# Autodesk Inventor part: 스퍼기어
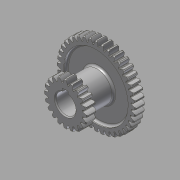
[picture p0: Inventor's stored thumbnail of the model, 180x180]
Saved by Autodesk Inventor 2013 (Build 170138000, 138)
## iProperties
Created: 2015-09
Part Number: 스퍼기어
Material: 강철, 연강
Document SubType Name: Modeling
Designer: mduedu
Density: 7.86 g/cm^3
Mass: 345.726 g
Surface Area: 225.641 cm^2
Volume: 43.9855 cm^3
Author: mduedu
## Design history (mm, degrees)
sketch "스케치1"
  geometry: C1 r 38 at (0, 0); C2 r 40 at (0, 0); C3 r 35.5 at (0, 0); 1 further point
  constraints: 3 centre point, 3 coincident
  dimensions: "d0" = 76 diameter of C1; "d2" = 2 radial gap between concentric circles of C2 C1; "d3" = 71 diameter of C3 (computed from d0)
extrude "돌출1" new body sketch "스케치1" stored distance "d4" = 10; taper "d5" = 0 deg
sketch "스케치2"
  geometry: L1 (0, 35.5)-(0, -35.5); L2 (0, 0)-(40, 0); L3 (0, 0.57)-(39.996, 0.57); L4 (0, 1.57)-(39.969, 1.57); L5 (0, 2.07)-(39.946, 2.07); A1 r 35.5 centre (0, 0) between (0, 35.5) and (0, -35.5) reference; A2 r 40 centre (0, 0) between (40, 0) and (39.946, 2.07) reference; A3 r 9.234 centre (34.93, -7.149) between (39.996, 0.57) and (35.44, 2.07); A4 r 9.234 centre (34.93, 7.149) between (35.44, -2.07) and (39.996, -0.57); A5 r 40 centre (0, 0) between (39.996, -0.57) and (39.996, 0.57); A6 r 35.5 centre (0, 0) between (35.44, -2.07) and (35.44, 2.07); 4 further points
  constraints: 16 point on circle, 10 end point, 6 point on line, 4 centre point, 3 coincident, 3 parallel, 3 symmetric about line, 2 midpoint, 1 perpendicular, 1 vertical, 3 other
  dimensions: "d6" = 0.5 distance between parallel lines of L4 L5; "d8" = 1 distance between parallel lines of L3 L4; "d9" = 1.57 distance between parallel lines of L2 L4
extrude "돌출2" join sketch "스케치2" distance "d10" = 5; taper "d12" = 0 deg; dims "d11" = 5, "d13" = 0
fillet "모깎기1" dims "d17" = 0.5
chamfer "모따기1" distance "d21" = 1; stored, may be unused: second distance "d22" = 2, angle "d23" = 45 deg
sketch "스케치3"
  geometry: C1 r 32.5 at (0, 0); C2 r 15 at (0, 0); 1 further point
  constraints: 2 centre point, 2 coincident
  dimensions: "d27" = 65 diameter of C1; "d28" = 30 diameter of C2
extrude "돌출3" cut sketch "스케치3" distance "d29" = 3; taper "d30" = 0 deg
fillet "모깎기2" dims "d31" = 2
node "작업 평면2"
  node "작업 평면1"
sketch "스케치4"
  geometry: C1 r 15 at (0, 0) reference; 1 further point
extrude "돌출4" join sketch "스케치4" stored distance "d34" = 3; taper "d35" = 0 deg
sketch "스케치5"
  geometry: C1 r 17.5 at (0, 0); C2 r 20 at (0, 0); C3 r 22 at (0, 0); 1 further point
  constraints: 3 centre point, 3 coincident
  dimensions: "d36" = 40 diameter of C2; "d38" = 2 radial gap between concentric circles of C2 C3; "d39" = 35 diameter of C1 (= d36 - 2.5 x d38)
extrude "돌출6" join sketch "스케치5" distance "d46" = 10; taper "d47" = 0 deg
sketch "스케치6"
  geometry: L1 (0, 0)-(0, 22); L2 (-17.5, 0)-(17.5, 0); L3 (-0.57, 0)-(-0.57, 21.993); L4 (-1.57, 0)-(-1.57, 21.944); L5 (-2.07, 0)-(-2.07, 21.902); A1 r 22 centre (0, 0) between (0, 22) and (-0.57, 21.993) reference; A2 r 17.5 centre (0, 0) between (-17.5, 0) and (17.5, 0) reference; A3 r 9.431 centre (7.348, 16.868) between (-0.57, 21.993) and (-2.07, 17.377); A4 r 9.431 centre (-7.348, 16.868) between (2.07, 17.377) and (0.57, 21.993); A5 r 17.5 centre (0, 0) between (2.07, 17.377) and (-2.07, 17.377); A6 r 22 centre (0, 0) between (0.57, 21.993) and (-0.57, 21.993); 4 further points
  constraints: 16 point on circle, 10 end point, 5 point on line, 4 centre point, 3 coincident, 3 symmetric about line, 2 parallel, 2 perpendicular, 1 midpoint, 1 vertical, 3 other
  dimensions: "d40" = 0.5 distance between parallel lines of L4 L5; "d42" = 1 distance between parallel lines of L3 L4; "d43" = 1.57 distance between parallel lines of L1 L4
extrude "돌출5" join sketch "스케치6" distance "d44" = 10; taper "d45" = 0 deg
fillet "모깎기3" dims "d48" = 0.5
chamfer "모따기2" distance "d49" = 1; stored, may be unused: second distance "d50" = 2, angle "d51" = 45 deg
sketch "스케치7"
  geometry: C1 r 10 at (0, 0); 1 further point
  constraints: 1 centre point, 1 coincident
  dimensions: "d55" = 20 diameter of C1
extrude "돌출7" cut sketch "스케치7" stored distance "d56" = 10; taper "d57" = 0 deg
sketch "스케치8"
  geometry: L1 (-9.539, -3)-(-12.8, -3); L2 (-12.8, -3)-(-12.8, 3); L3 (-12.8, 3)-(-9.539, 3); L4 (-9.539, 3)-(-9.539, -3); A1 r 10 centre (0, 0) between (-9.539, -3) and (-9.539, 3) reference; 2 further points
  constraints: 8 end point, 3 point on circle, 2 parallel, 1 horizontal, 1 horizontal alignment, 1 perpendicular
  dimensions: "d58" = 6 distance of L1.end L2.end; "d60" = 22.8 distance from line of point (10, 0) L2
extrude "돌출8" cut sketch "스케치8" stored distance "d61" = 10; taper "d62" = 0 deg
chamfer "모따기3" distance "d63" = 1; stored, may be unused: second distance "d64" = 2, angle "d65" = 45 deg
fillet "모깎기4" dims "d66" = 2
node "솔리드1"
pattern_circular "원형 패턴3" dims "d25" = 360 deg
mirror "대칭1"
pattern_circular "원형 패턴4" dims "d53" = 360 deg
other parameters: "d32" = 9
